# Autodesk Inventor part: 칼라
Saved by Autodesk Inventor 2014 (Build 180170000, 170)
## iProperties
Created: 2026-08
Part Number: 칼라
Material: 일반
Document SubType Name: Modeling
Designer: dg
Density: 1 g/cm^3
Appearance: 기본값
Author: dg
Author: jhkim
Creation Date: 2026-07-31
Sending System: Autodesk Inventor 2027
Preprocessor: ST-DEVELOPER v20.1
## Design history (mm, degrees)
node "칼라1"
node "솔리드1"
node "기준1"
